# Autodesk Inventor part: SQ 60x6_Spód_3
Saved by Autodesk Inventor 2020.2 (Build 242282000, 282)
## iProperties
Created: 2006-08
Part Number: SQ 60x6_Spód_3
Material: Ogólny
Document SubType Name: Modeling
Designer: F.Stasiak
Manufacturer: Standard
Standards Organization: Custom
Stock Number: DIN EN 10210-2 SQ 60x6
Density: 1 g/cm^3
Appearance: Domyślna
Manager: www.cadconsulting.pl
Company: Fabian Stasiak CAD Consulting
G_L: 1500,0 mm
G_W: 60,000 mm
G_H: 60,000 mm
AFG_Item: 60 x 60 x 6
Author: F.Stasiak
Subject: Zbiór ćwiczeń. Autodesk Inventor 2020. Kurs podstawowy
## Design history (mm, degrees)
sketch "AFG_Detailed"
  geometry: L1 (-12, 54)-(-48, 54); L2 (-54, 48)-(-54, 12); L3 (-48, 6)-(-12, 6); L4 (-6, 12)-(-6, 48); L5 (-12, 60)-(-48, 60); L6 (-60, 48)-(-60, 12); L7 (-48, 0)-(-12, 0); L8 (0, 12)-(0, 48); A1 r 6 centre (-12, 48) between (-6, 48) and (-12, 54); A2 r 12 centre (-12, 48) between (0, 48) and (-12, 60); A3 r 6 centre (-12, 12) between (-12, 6) and (-6, 12); A4 r 12 centre (-12, 12) between (-12, 0) and (0, 12); A5 r 12 centre (-48, 12) between (-60, 12) and (-48, 0); A6 r 6 centre (-48, 12) between (-54, 12) and (-48, 6); A7 r 6 centre (-48, 48) between (-48, 54) and (-54, 48); A8 r 12 centre (-48, 48) between (-48, 60) and (-60, 48); 4 further points
  constraints: 16 end point, 16 point on circle, 16 tangent, 8 centre point, 6 point on line, 4 parallel, 2 perpendicular, 1 vertical
  dimensions: "d15" = 60 distance of point (-60, 0) point (0, 0) (= GEO_B); "d16" = 6 distance between parallel lines of L7 L3 (= GEO_S); "d17" = 6 distance between parallel lines of L8 L4 (= GEO_S); "d18" = 6 distance between parallel lines of L5 L1 (= GEO_S); "d19" = 6 distance between parallel lines of L6 L2 (= GEO_S); "d20" = 30 distance from line of point (-30, 30) L7 (= 0.5 x GEO_H); "d30" = 6 radius of A1 (= GEO_R1 - GEO_S); "GEO_R1" = 12 radius of A2; "d32" = 6 radius of A3 (= GEO_R1 - GEO_S); "d33" = 12 radius of A4 (= GEO_R1); "d34" = 12 radius of A5 (= GEO_R1); "d35" = 6 radius of A6 (= GEO_R1 - GEO_S); "d36" = 6 radius of A7 (= GEO_R1 - GEO_S); "d37" = 12 radius of A8 (= GEO_R1); "d38" = 30 distance from line of L6 point (-30, 30) (= 0.5 x GEO_B); "d39" = 60 distance between parallel lines of L7 L5 (= GEO_H)
sketch "AFG_Medium"
  geometry: L1 (-6, 54)-(-54, 54); L2 (-54, 54)-(-54, 6); L3 (-54, 6)-(-6, 6); L4 (-6, 6)-(-6, 54); L5 (0, 60)-(-60, 60); L6 (-60, 60)-(-60, 0); L7 (-60, 0)-(0, 0); L8 (0, 0)-(0, 60); 1 further point
  constraints: 16 end point, 4 parallel, 2 perpendicular, 1 vertical
  dimensions: "GEO_B" = 60 distance of L6.end L7.end; "GEO_S" = 6 distance between parallel lines of L7 L3; "d5" = 6 distance between parallel lines of L8 L4 (= GEO_S); "d6" = 6 distance between parallel lines of L5 L1 (= GEO_S); "d7" = 6 distance between parallel lines of L6 L2 (= GEO_S); "d12" = 30 distance from line of point (-30, 30) L7 (= 0.5 x GEO_H); "d40" = 60 distance between parallel lines of L7 L5 (= GEO_H); "d41" = 30 distance from line of L6 point (-30, 30) (= 0.5 x GEO_B)
sketch "AFG_Simplified"
  geometry: L1 (0, 60)-(-60, 60); L2 (-60, 60)-(-60, 0); L3 (-60, 0)-(0, 0); L4 (0, 0)-(0, 60); 1 further point
  constraints: 8 end point, 2 parallel, 1 perpendicular, 1 vertical
  dimensions: "d23" = 60 distance of L2.end L3.end (= GEO_B); "d28" = 30 distance from line of point (-30, 30) L3 (= 0.5 x GEO_H); "d42" = 60 distance between parallel lines of L3 L1 (= GEO_H); "d43" = 30 distance from line of point (-30, 30) L2 (= 0.5 x GEO_B)
derived "Szkielet podstawy.ipt"
  sketch "Szkic1"
    geometry: L1 (0, 0)-(1500, 0) reference; L2 (1500, 0)-(1500, 1000) reference; L3 (1500, 1000)-(0, 1000) reference; L4 (0, 1000)-(0, 0) reference
  sketch "Szkic2"
    geometry: L1 (0, 1000)-(0, 0) reference; L2 (0, 0)-(1500, 0) reference; L3 (1500, 0)-(1500, 1000) reference; L4 (500, 1000)-(1500, 1000) reference; L5 (1500, 1000)-(1500, 0) reference; L6 (1500, 0)-(500, 0) reference; L7 (500, 0)-(500, 1000) reference; L8 (1500, 1000)-(0, 1000) reference
node "AFG_StartWorkPoint_SQ 60x6_Spód_3"
node "AFG_EndWorkPoint_SQ 60x6_Spód_3"
node "AFG_HelpAxis"
node "AFG_HelpStart"
node "AFG_HelpEnd"
node "AFG_Midplane"
  node "AFG_Startplane"
  node "AFG_EndPlane"
node "AFG_Profile_AxisX_for_External_Matrix"
extrude "AFG_Detailed_SQ 60x6_Spód_3" join sketch "AFG_Detailed" stored distance "d49" = 0.13; taper "d50" = 0 deg
extrude "AFG_Simplified_SQ 60x6_Spód_3" join sketch "AFG_Simplified" stored distance "d51" = 0.13; taper "d52" = 0 deg
node "AFG_StartWorkPoint_SQ 60x6_Spód_2"
node "AFG_EndWorkPoint_SQ 60x6_Spód_2"
node "AFG_STARTCUTPLANE_SQ 60x6_Spód_3"
node "AFG_StartWorkPoint_SQ 60x6_Spód_4"
node "AFG_EndWorkPoint_SQ 60x6_Spód_4"
node "AFG_ENDCUTPLANE_SQ 60x6_Spód_3"
node "Bryła1"
node "Korpusy bryłowe"
node "Korpusy powierzchniowe"
other parameters: "GEO_H" = 60, "AFG_Origin_X" = 0 (= 0 x GEO_B) [user parameter], "AFG_Origin_Y" = 0 (= 0 x GEO_H) [user parameter], "AFG_IP_X2" = 0 (= 0 x GEO_B) [user parameter], "AFG_IP_Y4" = 0 (= 0 x GEO_H) [user parameter], "AFG_IP_X6" = 0 (= 0 x GEO_B) [user parameter], "AFG_IP_Y8" = 0 (= 0 x GEO_H) [user parameter], "d47" = 0, "d48" = 0, "G_L" = 1500 [user parameter], "d55" = 0, "d58" = 0
